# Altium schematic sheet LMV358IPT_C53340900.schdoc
size 127 x 101 mm
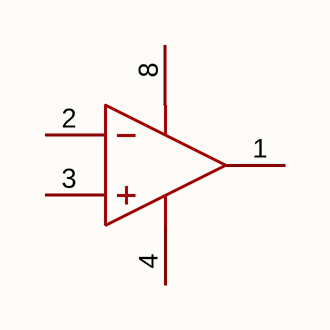
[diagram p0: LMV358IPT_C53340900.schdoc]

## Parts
U?  lmv358ipt(tp)  [TSSOP-8_L4.4-W3.0-P0.65-LS6.4-BL]  (value not drawn)  (part A of 2)

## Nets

Not connected (* = marked no-connect by the designer): U? 1(OUT_A) 2(IN_A-) 3(IN_A+) 4(V-) 8(V+)

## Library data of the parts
U? = lmv358ipt(tp): 放大器数:2;轨到轨:轨到轨输入,轨到轨输出;增益带宽积(GBW):1MHz;输入失调电压(Vos):5mV;压摆率(SR):-;输入偏置电流(Ib):10pA;; Manufacturer: TECH PUBLIC(台舟); AddInBom: yes; SymbolName: LMV358IPT_C53340900; ModelId: 85577802f9634e7e85ffa2fd25a37b6f; ModelName: TSSOP-8_L4.4-W3.0-P0.65-LS6.4-BL-2; ModelTransform: 118.11,251.968,0,0,0,0,0,0,0; Number of Channels: 2; Gain Bandwidth Product: 1MHz; Vos - Input Offset Voltage: 5mV; Input Offset Voltage Drift(Vos TC): 650nV/℃; Ib - Input Bias Current: 10pA; Common Mode Rejection Ratio(CMRR): 95dB; Quiescent Current: 50uA; Output Current: 20mA; Single supply: 2.1V~5.5V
